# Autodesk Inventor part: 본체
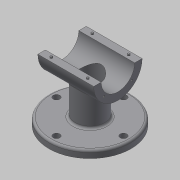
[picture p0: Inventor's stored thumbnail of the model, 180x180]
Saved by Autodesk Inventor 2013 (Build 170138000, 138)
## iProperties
Created: 2015-12
Part Number: 본체
Material: 일반
Document SubType Name: Modeling
Designer: mduedu
Density: 2.71 g/cm^3
Author: mduedu
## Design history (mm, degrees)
sketch "스케치1"
  geometry: C1 r 55 at (0, 0); 1 further point
  constraints: 1 centre point, 1 coincident
  dimensions: "d124" = 110 diameter of C1
extrude "돌출1" new body sketch "스케치1" distance "d3" = 10; taper "d4" = 0 deg
sketch "스케치2"
  geometry: C1 r 32.5 at (80, 0); 1 further point
  constraints: 1 centre point, 1 horizontal alignment
  dimensions: "d5" = 65 diameter of C1; "d125" = 80 distance of C1.centre point (0, 0)
extrude "돌출2" join sketch "스케치2" stored distance "d7" = 75; taper "d8" = 0 deg
sketch "스케치3"
  geometry: C1 r 20 at (0, 0); 1 further point
  constraints: 1 centre point, 1 coincident
  dimensions: "d154" = 40 diameter of C1
extrude "돌출3" new body sketch "스케치3" stored distance "d12" = 75; taper "d13" = 0 deg
feature "결합1"
  node "솔리드2"
fillet "모깎기13" dims "d155" = 3
fillet "모깎기7" dims "d41" = 3
hole "구멍2" diameter "d44" = 45; stored, may be unused: countersink angle "d48" = 90 deg, drill point angle "d50" = 118 deg; dims "d42" = 10, "d43" = 10, "d45" = 6, "d46" = 4, "d47" = 2, "d49" = 8
sketch "스케치7" dims "d52" = 26.5
  geometry: L1 (0, 0)-(32.5, 0); L2 (0, 0)-(22.981, 22.981); A1 r 32.5 centre (0, 0) between (32.5, 0) and (22.981, 22.981) reference; 3 further points
  constraints: 4 end point, 2 point on circle, 1 coincident, 1 horizontal, 1 point on line, 3 other
  dimensions: "d51" = 45 deg angle of L2 L1
hole "구멍3" sketch "스케치7" at (18.738, 18.738) diameter "d54" = 2.459; stored, may be unused: countersink angle "d58" = 90 deg, drill point angle "d60" = 118 deg; dims "d55" = 8, "d56" = 4, "d57" = 2, "d59" = 10
sketch "스케치9"
  geometry: L1 (-75, 82.5)-(75, 82.5); L2 (75, 82.5)-(75, 0); L3 (75, 0)-(-75, 0); L4 (-75, 0)-(-75, 82.5); C1 r 32.5 at (0, 0) reference; 2 further points
  constraints: 8 end point, 2 parallel, 1 coincident, 1 horizontal, 1 midpoint, 1 perpendicular
  dimensions: "d71" = 50 distance edge to line of C1 L1; "d116" = 150 distance between parallel lines of L2 L4
extrude "돌출5" cut sketch "스케치9" stored distance "d73" = 0; taper "d74" = 0 deg
node "작업 평면1"
sketch "스케치10"
  geometry: C1 r 15 at (0, 0); 1 further point
  constraints: 1 centre point, 1 coincident
  dimensions: "d156" = 30 diameter of C1
extrude "돌출6" cut sketch "스케치10" stored distance "d78" = 50; taper "d79" = 0 deg
sketch "스케치11"
  geometry: 2 further points
  constraints: 1 coincident
hole "구멍4" sketch "스케치11" at (0, 0) diameter "d81" = 12; stored, may be unused: countersink angle "d85" = 90 deg, drill point angle "d87" = 118 deg; dims "d82" = 8, "d83" = 30, "d84" = 10, "d86" = 10
sketch "스케치12"
  geometry: C1 r 10 at (0, 0); 1 further point
  constraints: 1 centre point, 1 coincident
  dimensions: "d88" = 20 diameter of C1
extrude "돌출7" cut sketch "스케치12" distance "d89" = 10; taper "d90" = 0 deg
chamfer "모따기1" distance "d91" = 1; stored, may be unused: second distance "d92" = 2, angle "d93" = 45 deg
sketch "스케치15"
  geometry: L1 (-75, 55)-(-75, 65) reference; L2 (0, 65)-(0, 55) reference; L3 (-75, 60)-(0, 60); C1 r 1.5 at (-62, 60); 1 further point
  constraints: 2 end point, 2 midpoint, 1 centre point, 1 point on line
  dimensions: "d117" = 3 diameter of C1; "d118" = 13 distance from line of C1.centre L1
extrude "돌출8" join sketch "스케치15" distance "d119" = 1.8; taper "d120" = 0 deg
chamfer "모따기2" distance "d121" = 0.5; stored, may be unused: second distance "d122" = 2, angle "d123" = 45 deg
sketch "스케치18" dims "d141" = 90
  geometry: C1 r 52 at (0, 0) reference; 2 further points
  constraints: 2 vertical alignment, 1 coincident, 2 other
hole "구멍8" sketch "스케치18" at (0, 45) diameter "d142" = 9; stored, may be unused: countersink angle "d146" = 90 deg, drill point angle "d148" = 118 deg; dims "d143" = 6, "d144" = 4, "d145" = 2, "d147" = 8
node "솔리드1"
pattern_circular "원형 패턴1" dims angle "d62" = 360 deg
mirror "대칭3"
mirror "대칭5"
mirror "대칭6"
pattern_circular "원형 패턴2" dims angle "d150" = 360 deg
